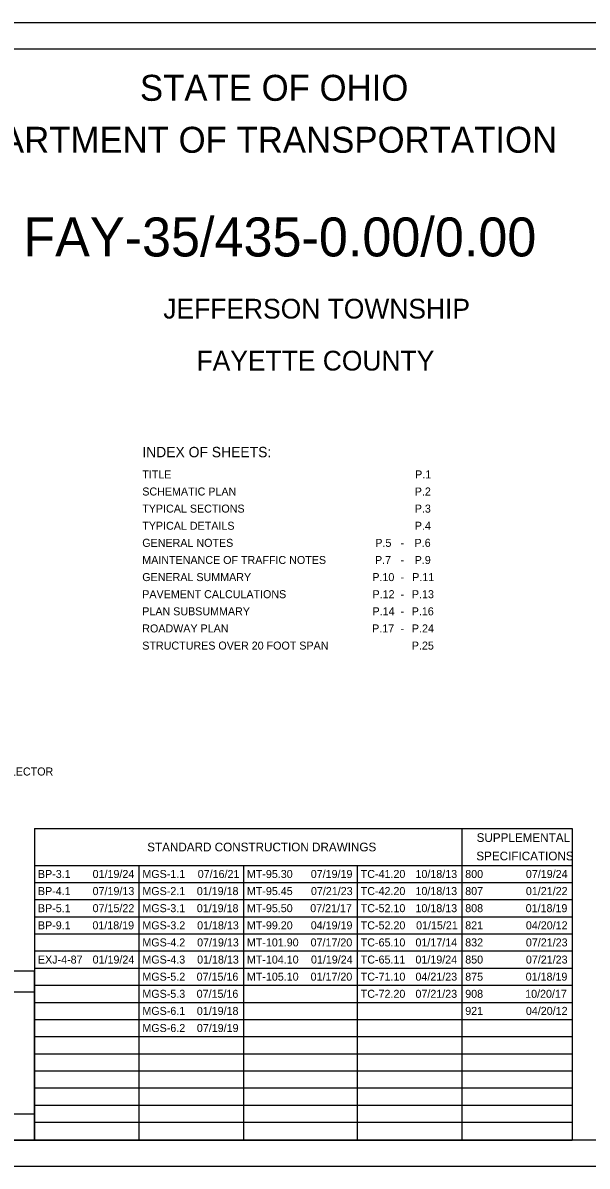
# Model space of a CAD drawing. Extents: x 0 to 34, y 0 to 22.
# Drawn here: x 11.54 to 22.4, y 0 to 22 of the extents above; entities that cross this region are included whole.
import ezdxf

# ---------------------------------------------------------------- set-up
doc = ezdxf.new("R2010")
doc.units = 0
for name, color, linetype in [('SH_Border', 7, 'Continuous'), ('SH_Cut_Line', 7, 'Continuous'), ('SH_Data', 7, 'Continuous'), ('SH_Text', 7, 'Continuous')]:
    doc.layers.add(name, color=color, linetype=linetype)

msp = doc.modelspace()

# ---------------------------------------------------------------- linework, layer by layer
at = {"layer": 'SH_Border'}
msp.add_lwpolyline([(1.5, 21.5), (33.5, 21.5), (33.5, 0.5), (1.5, 0.5)], close=True, dxfattribs=at)
at = {"layer": 'SH_Cut_Line'}
msp.add_lwpolyline([(0, 0), (34, 0), (34, 22), (0, 22)], close=True, dxfattribs=at)
at = {"layer": 'SH_Data'}
for p, q in [((11.767, 3.75), (8.967, 3.75)), ((11.767, 0.5), (11.767, 3.75)), ((11.767, 3.35), (8.967, 3.35))]:
    msp.add_line(p, q, dxfattribs=at)
msp.add_lwpolyline([(11.767, 0.5), (11.767, 1), (8.967, 1), (8.967, 0.5)], close=True, dxfattribs=at)
at = {"layer": 'SH_Text'}
for p, q in [((11.767, 6.495), (22.111, 6.495)), ((11.767, 6.495), (11.767, 0.5)), ((19.986, 6.495), (19.986, 0.5)), ((22.111, 6.495), (22.111, 0.5)), ((11.767, 5.787), (22.111, 5.787)), ((13.776, 5.787), (13.776, 0.5)), ((15.786, 5.787), (15.786, 0.5)), ((17.976, 5.787), (17.976, 0.5)), ((11.767, 5.458), (22.111, 5.458)), ((11.767, 5.128), (22.111, 5.128)), ((11.767, 4.799), (22.111, 4.799)), ((11.767, 4.469), (22.111, 4.469)), ((11.767, 4.14), (22.111, 4.14)), ((11.767, 3.811), (22.111, 3.811)), ((11.767, 3.481), (22.111, 3.481)), ((11.767, 3.152), (22.111, 3.152)), ((11.767, 2.822), (22.111, 2.822)), ((11.767, 2.493), (22.111, 2.493)), ((11.767, 2.164), (22.111, 2.164)), ((11.767, 1.834), (22.111, 1.834)), ((11.767, 1.505), (22.111, 1.505)), ((11.767, 1.175), (22.111, 1.175)), ((11.767, 0.846), (22.111, 0.846)), ((11.767, 0.5), (22.111, 0.5))]:
    msp.add_line(p, q, dxfattribs=at)

# ---------------------------------------------------------------- texts
for s, height, p in [('STATE OF OHIO', 0.5, (13.795, 20.5)), ('DEPARTMENT OF TRANSPORTATION', 0.5, (9.747, 19.5)), ('FAY-35/435-0.00/0.00', 0.75, (11.551, 17.505)), ('JEFFERSON TOWNSHIP', 0.38, (14.244, 16.31)), ('FAYETTE COUNTY', 0.38, (14.884, 15.31)), ('INDEX OF SHEETS:', 0.2, (13.84, 13.641)), ('TITLE', 0.154, (13.84, 13.234)), ('P.1', 0.154, (19.088, 13.234)), ('SCHEMATIC PLAN', 0.154, (13.84, 12.905)), ('P.2', 0.154, (19.082, 12.905)), ('TYPICAL SECTIONS', 0.154, (13.84, 12.576)), ('P.3', 0.154, (19.082, 12.576)), ('TYPICAL DETAILS', 0.154, (13.84, 12.246)), ('P.4', 0.154, (19.082, 12.246)), ('GENERAL NOTES', 0.154, (13.84, 11.917)), ('P.5', 0.154, (18.323, 11.917)), ('-', 0.154, (18.808, 11.917)), ('P.6', 0.154, (19.078, 11.917)), ('MAINTENANCE OF TRAFFIC NOTES', 0.154, (13.84, 11.587)), ('P.7', 0.154, (18.317, 11.587)), ('P.9', 0.154, (19.08, 11.587)), ('-', 0.154, (18.808, 11.587)), ('GENERAL SUMMARY', 0.154, (13.84, 11.258)), ('P.10', 0.154, (18.265, 11.258)), ('-', 0.154, (18.808, 11.258)), ('P.11', 0.154, (19.033, 11.258)), ('PAVEMENT CALCULATIONS', 0.154, (13.84, 10.929)), ('P.12', 0.154, (18.269, 10.929)), ('P.13', 0.154, (19.027, 10.929)), ('-', 0.154, (18.808, 10.929)), ('PLAN SUBSUMMARY', 0.154, (13.84, 10.599)), ('P.14', 0.154, (18.269, 10.599)), ('-', 0.154, (18.808, 10.599)), ('P.16', 0.154, (19.023, 10.599)), ('ROADWAY PLAN', 0.154, (13.84, 10.27)), ('P.17', 0.154, (18.262, 10.27)), ('P.24', 0.154, (19.027, 10.27)), ('-', 0.154, (18.808, 10.27)), ('STRUCTURES OVER 20 FOOT SPAN', 0.154, (13.84, 9.94)), ('P.25', 0.154, (19.025, 9.94)), ('05 MAJOR COLLECTOR', 0.154, (9.805, 7.517)), ('SUPPLEMENTAL', 0.168, (20.271, 6.238)), ('STANDARD CONSTRUCTION DRAWINGS', 0.168, (13.935, 6.057)), ('SPECIFICATIONS', 0.168, (20.265, 5.884)), ('BP-3.1', 0.154, (11.833, 5.545)), ('01/19/24', 0.154, (12.885, 5.545)), ('MGS-1.1', 0.154, (13.842, 5.545)), ('07/16/21', 0.154, (14.907, 5.545)), ('MT-95.30', 0.154, (15.852, 5.545)), ('07/19/19', 0.154, (17.081, 5.545)), ('TC-41.20', 0.154, (18.042, 5.545)), ('10/18/13', 0.154, (19.095, 5.545)), ('800', 0.154, (20.052, 5.545)), ('07/19/24', 0.154, (21.219, 5.545)), ('BP-4.1', 0.154, (11.833, 5.216)), ('07/19/13', 0.154, (12.885, 5.216)), ('MGS-2.1', 0.154, (13.842, 5.216)), ('01/19/18', 0.154, (14.889, 5.216)), ('MT-95.45', 0.154, (15.852, 5.216)), ('07/21/23', 0.154, (17.085, 5.216)), ('TC-42.20', 0.154, (18.042, 5.216)), ('10/18/13', 0.154, (19.095, 5.216)), ('807', 0.154, (20.052, 5.216)), ('01/21/22', 0.154, (21.219, 5.216)), ('BP-5.1', 0.154, (11.833, 4.887)), ('07/15/22', 0.154, (12.885, 4.887)), ('MGS-3.1', 0.154, (13.842, 4.887)), ('01/19/18', 0.154, (14.889, 4.887)), ('MT-95.50', 0.154, (15.852, 4.887)), ('07/21/17', 0.154, (17.071, 4.887)), ('TC-52.10', 0.154, (18.042, 4.887)), ('10/18/13', 0.154, (19.095, 4.887)), ('808', 0.154, (20.052, 4.887)), ('01/18/19', 0.154, (21.215, 4.887)), ('BP-9.1', 0.154, (11.833, 4.557)), ('01/18/19', 0.154, (12.881, 4.557)), ('MGS-3.2', 0.154, (13.842, 4.557)), ('01/18/13', 0.154, (14.895, 4.557)), ('MT-99.20', 0.154, (15.852, 4.557)), ('04/19/19', 0.154, (17.081, 4.557)), ('TC-52.20', 0.154, (18.042, 4.557)), ('01/15/21', 0.154, (19.107, 4.557)), ('821', 0.154, (20.052, 4.557)), ('04/20/12', 0.154, (21.219, 4.557)), ('MGS-4.2', 0.154, (13.842, 4.228)), ('07/19/13', 0.154, (14.895, 4.228)), ('MT-101.90', 0.154, (15.852, 4.228)), ('07/17/20', 0.154, (17.078, 4.228)), ('TC-65.10', 0.154, (18.042, 4.228)), ('01/17/14', 0.154, (19.095, 4.228)), ('832', 0.154, (20.052, 4.228)), ('07/21/23', 0.154, (21.219, 4.228)), ('EXJ-4-87', 0.154, (11.833, 3.898)), ('01/19/24', 0.154, (12.885, 3.898)), ('MGS-4.3', 0.154, (13.842, 3.898)), ('01/18/13', 0.154, (14.895, 3.898)), ('MT-104.10', 0.154, (15.852, 3.898)), ('01/19/24', 0.154, (17.085, 3.898)), ('TC-65.11', 0.154, (18.042, 3.898)), ('01/19/24', 0.154, (19.095, 3.898)), ('850', 0.154, (20.052, 3.898)), ('07/21/23', 0.154, (21.219, 3.898)), ('MGS-5.2', 0.154, (13.842, 3.569)), ('07/15/16', 0.154, (14.886, 3.569)), ('MT-105.10', 0.154, (15.852, 3.569)), ('01/17/20', 0.154, (17.078, 3.569)), ('TC-71.10', 0.154, (18.042, 3.569)), ('04/21/23', 0.154, (19.095, 3.569)), ('875', 0.154, (20.052, 3.569)), ('01/18/19', 0.154, (21.215, 3.569)), ('MGS-5.3', 0.154, (13.842, 3.239)), ('07/15/16', 0.154, (14.886, 3.239)), ('TC-72.20', 0.154, (18.042, 3.239)), ('07/21/23', 0.154, (19.095, 3.239)), ('908', 0.154, (20.052, 3.239)), ('10/20/17', 0.154, (21.205, 3.239)), ('MGS-6.1', 0.154, (13.842, 2.91)), ('01/19/18', 0.154, (14.889, 2.91)), ('921', 0.154, (20.052, 2.91)), ('04/20/12', 0.154, (21.219, 2.91)), ('MGS-6.2', 0.154, (13.842, 2.581)), ('07/19/19', 0.154, (14.89, 2.581))]:
    msp.add_text(s, height=height, dxfattribs=at).set_placement(p)

doc.saveas('drawing.dxf')
